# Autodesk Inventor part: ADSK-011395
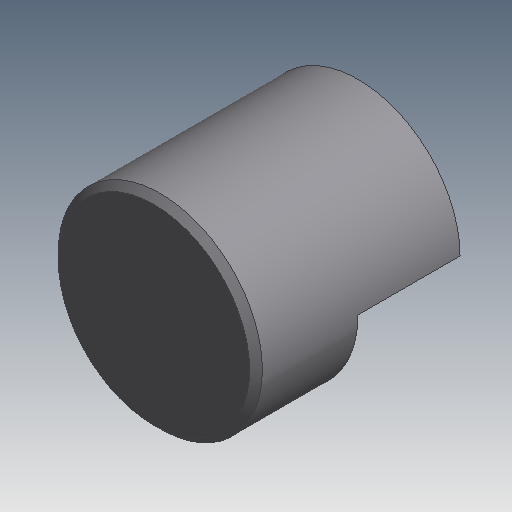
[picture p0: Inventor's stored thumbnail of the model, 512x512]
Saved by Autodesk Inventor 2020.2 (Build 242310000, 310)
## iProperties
Created: 2000-02
Part Number: ADSK-011395
Material: Pearson HRS
Document SubType Name: Modeling
Designer: glanglot
Density: 7.83 g/cm^3
Appearance: Métal - Acier
Mass: 66.5287 g
Surface Area: 31.0716 cm^2
Volume: 8.49664 cm^3
Control State: 0
Checked Out: False
Master: False
Shininess: 0.0
Length Units: 11272
Angle Units: 11279
Time Units: 11290
Mass Units: 11286
Length Display Precision: 3
Angle Display Precision: 2
Compacted: True
CUTLENGTH: 1.13
MATERIAL_NUMBER: A084576
Dimensions: 1x1x1 in
Mass: 0,147 lb
VLT_Material: Pearson HRS
Density: 0.0
Volumn: 0.0
Area: 0.0
PropertySet Name: Model Information
Author: glanglot
Revision Number: -
Title: ADSK-011395
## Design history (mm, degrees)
node "Extrusion1" dims "d1" = 25.4, "d2" = 0
node "Extrusion2" dims "d4" = 12.7, "d5" = 0
node "Hole1" dims "d6" = 6.4008, "d7" = 9.525, "d8" = 6.35, "d9" = 60 deg, "d10" = 9.525, "d11" = 118 deg
node "Chamfer1" dims "d12" = 0.79375, "d13" = 0.79375, "d14" = 45 deg
node "Solide1"
node "Corps solides"
node "Corps surfaciques"
sketch "Sketch1"
  geometry: C1 r 12.7 at (0, 0); 1 further point
  constraints: 1 centre point, 1 coincident
  dimensions: "d0" = 25.4 diameter of C1
sketch "Sketch2"
  geometry: L1 (0, -15.24)-(0, 20.32) reference; L2 (-20.32, 0)-(15.24, 0) reference; L3 (6.35, 0)-(12.7, 0); L4 (-6.35, 0)-(-12.7, 0); A1 r 12.7 centre (0, 0) between (12.7, 0) and (-12.7, 0) reference; A2 r 6.35 centre (0, 0) between (6.35, 0) and (-6.35, 0)
  constraints: 4 end point, 4 point on circle, 4 point on line, 1 centre point, 1 coincident
  dimensions: "d3" = 6.35 radius of A2
sketch "Sketch3"
  geometry: A1 r 12.7 centre (0, 0) between (-12.7, 0) and (12.7, 0) reference; 1 further point
  constraints: 1 coincident
